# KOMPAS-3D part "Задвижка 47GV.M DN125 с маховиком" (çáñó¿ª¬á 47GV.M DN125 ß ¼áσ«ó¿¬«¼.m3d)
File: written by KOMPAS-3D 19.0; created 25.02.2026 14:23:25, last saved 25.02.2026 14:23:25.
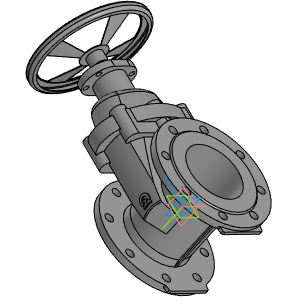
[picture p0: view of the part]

Document properties: Автор: Энергия; Полное имя файла: ..\..\47GVM\DR.47GVM.125.16.00.000\DR.47GVM.125.16.00.00 - Задвижка с обрезиненным клином DN125.a3d

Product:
- Part/product: Задвижка 47GV.M DN125 с маховиком
    Масса: 38.0104
    source file: 47GV.M DN125\DR.47GVM.125.16.00.00 - Задвижка с обрезиненным клином DN125.spw
  - Component: Задвижка с обрезиненным клином DN125. Сборочный чертеж  | designation DR.47GVM.125.16.00.00СБ  | pos. 0  | Масса: 25.3494; Раздел спецификации: Документация; Форматы листов документа: 2xA3; source file: 47GV.M DN125\DR.47GVM.125.16.00.000 СБ - Задвижка с обрезиненным клином DN125.cdw

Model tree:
1. Операция без истории:1

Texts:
  Точка начала. Х
  Точка начала. Y
  Точка начала. Z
